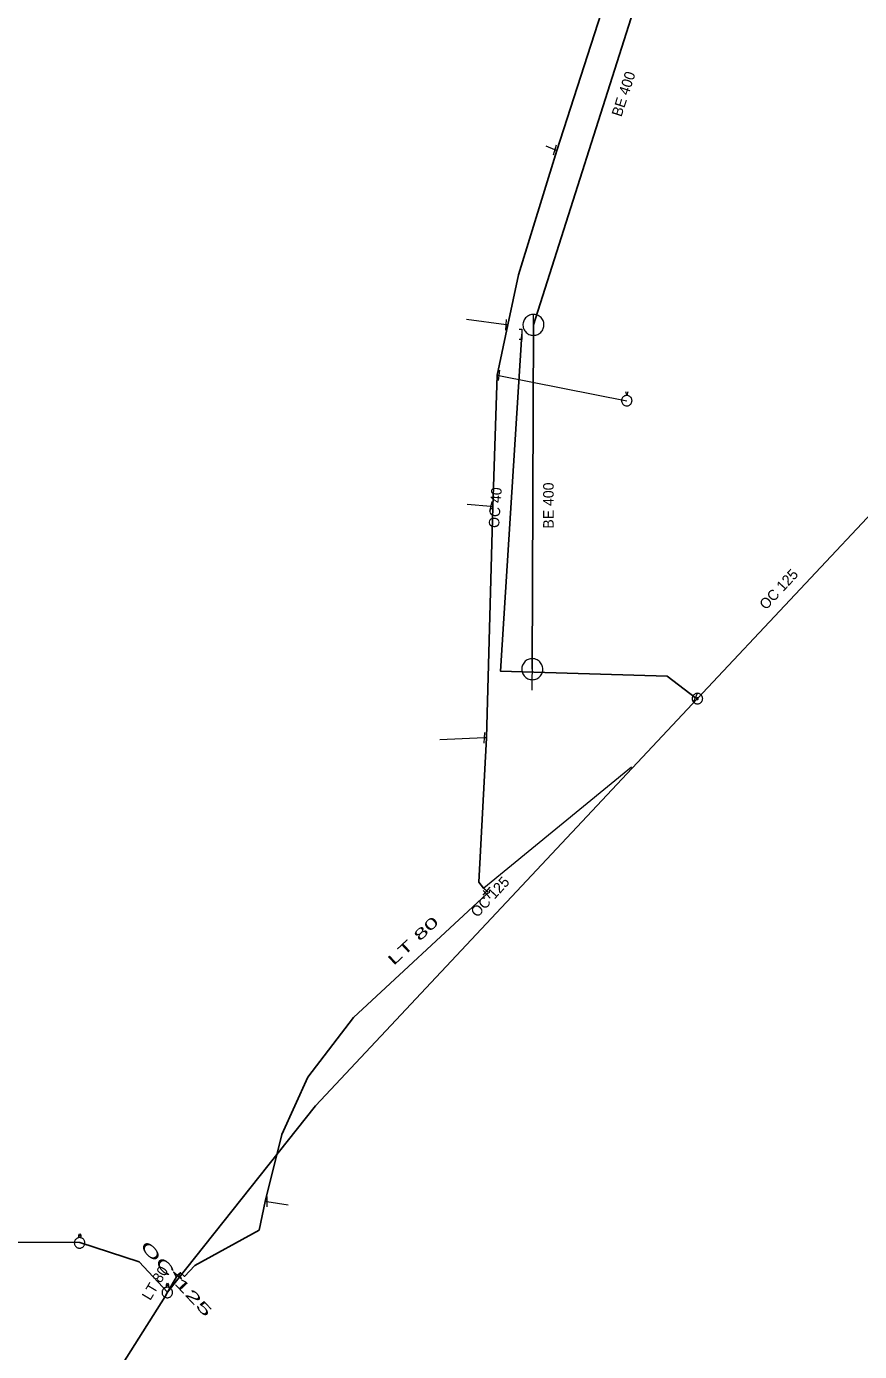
# Model space of a CAD drawing. Extents: x -659250 to -657316, y -997555 to -993684.
# Drawn here: x -658626.7 to -658547.5, y -994219.6 to -994093.6 of the extents above; entities that cross this region are included whole.
import ezdxf

# ---------------------------------------------------------------- set-up
doc = ezdxf.new("R2010")
doc.units = 0
doc.header["$LTSCALE"] = 0.4
doc.layers.add('1', color=7, linetype='Continuous')
for name, color, linetype, lineweight in [('13', 7, 'Continuous', 13), ('14', 7, 'Continuous', 25), ('17', 7, 'Continuous', 25), ('22', 7, 'Continuous', 13), ('23', 7, 'Continuous', 13), ('34', 7, 'Continuous', 13), ('47', 7, 'Continuous', 13)]:
    doc.layers.add(name, color=color, linetype=linetype, lineweight=lineweight)

msp = doc.modelspace()

# ---------------------------------------------------------------- linework, layer by layer
at = {"layer": '13'}
for p, q in [((-658576.454, -994105.35), (-658577.289, -994105.02)), ((-658581.1, -994121.989), (-658584.87, -994121.489)), ((-658581.8, -994126.809), (-658569.629, -994129.21)), ((-658582.539, -994139.27), (-658584.809, -994139.07)), ((-658583.155, -994161.27), (-658587.39, -994161.449)), ((-658583.218, -994175.535), (-658569.18, -994164.039)), ((-658603.864, -994205.37), (-658601.82, -994205.69))]:
    msp.add_line(p, q, dxfattribs=at)
at = {"layer": '14'}
for p, q in [((-658578.5, -994122), (-658563.75, -994075.64)), ((-658578.609, -994154.739), (-658578.5, -994122))]:
    msp.add_line(p, q, dxfattribs=at)
at = {"layer": '14', "lineweight": 13}
for p, q in [((-658576.27, -994105.41), (-658576.454, -994105.35)), ((-658580.94, -994122), (-658581.1, -994121.989)), ((-658581.96, -994126.789), (-658581.8, -994126.809)), ((-658582.379, -994139.309), (-658582.539, -994139.27)), ((-658562.909, -994157.543), (-658563.101, -994157.453)), ((-658582.98, -994161.28), (-658583.155, -994161.27)), ((-658583.26, -994175.57), (-658583.218, -994175.535)), ((-658604.01, -994205.37), (-658603.864, -994205.37))]:
    msp.add_line(p, q, dxfattribs=at)
msp.add_lwpolyline([(-658582.954, -994176.149), (-658582.77, -994175.98), (-658582.945, -994175.84)], dxfattribs=at)
at = {"layer": '17'}
for p, q in [((-658644.456, -994209.127), (-658621.638, -994209.272)), ((-658612.35, -994212.379), (-658613.3, -994213.989))]:
    msp.add_line(p, q, dxfattribs=at)
for points in [[(-658582.945, -994175.84), (-658583.26, -994175.57), (-658583.69, -994175), (-658582.98, -994161.28), (-658582.379, -994139.309), (-658581.96, -994126.789), (-658580.94, -994122), (-658579.92, -994117.25), (-658576.27, -994105.41), (-658571.09, -994089.289), (-658567.85, -994078.489), (-658564.5, -994070.01), (-658561.53, -994061.879), (-658555.69, -994047.969), (-658551.19, -994035.149), (-658548.489, -994027.129), (-658547.875, -994024.539)], [(-658563.101, -994157.453), (-658565.794, -994155.41), (-658581.649, -994154.919), (-658579.62, -994122.895)], [(-658533.629, -994132.381), (-658544.322, -994137.752), (-658562.909, -994157.543)], [(-658613.3, -994213.989), (-658599.228, -994196.254), (-658562.909, -994157.543)], [(-658612.35, -994212.379), (-658612.05, -994212.129), (-658611.69, -994212.48), (-658610.699, -994211.449), (-658604.579, -994208.079), (-658604.01, -994205.37), (-658602.44, -994198.98), (-658599.949, -994193.55), (-658595.629, -994187.85), (-658582.954, -994176.149)], [(-658621.638, -994209.272), (-658615.99, -994211.098), (-658613.3, -994213.989)], [(-658613.3, -994213.989), (-658613.524, -994214.403), (-658623.307, -994229.89), (-658624.14, -994257.537), (-658615.692, -994317.956), (-658606.899, -994352.517), (-658587.086, -994395.585), (-658588.159, -994408.494), (-658589.278, -994412.67), (-658589.404, -994413.139), (-658612.337, -994451.366), (-658612.825, -994451.789), (-658615.8, -994453.061)]]:
    msp.add_lwpolyline(points, dxfattribs=at)
at = {"layer": '22'}
for p, q in [((-658578.5, -994124), (-658578.499, -994121)), ((-658578.609, -994156.739), (-658578.608, -994153.739))]:
    msp.add_line(p, q, dxfattribs=at)
for points in [[(-658577.5, -994122), (-658577.505, -994121.891), (-658577.523, -994121.783), (-658577.553, -994121.677), (-658577.593, -994121.576), (-658577.645, -994121.479), (-658577.707, -994121.389), (-658577.779, -994121.306), (-658577.859, -994121.232), (-658577.947, -994121.166), (-658578.041, -994121.111), (-658578.141, -994121.066), (-658578.246, -994121.033), (-658578.353, -994121.011), (-658578.462, -994121.001), (-658578.572, -994121.003), (-658578.68, -994121.017), (-658578.787, -994121.042), (-658578.89, -994121.079), (-658578.988, -994121.128), (-658579.08, -994121.186), (-658579.166, -994121.255), (-658579.243, -994121.332), (-658579.312, -994121.418), (-658579.371, -994121.51), (-658579.419, -994121.608), (-658579.456, -994121.711), (-658579.482, -994121.818), (-658579.496, -994121.926), (-658579.499, -994122.036), (-658579.489, -994122.145), (-658579.468, -994122.252), (-658579.434, -994122.356), (-658579.39, -994122.456), (-658579.335, -994122.551), (-658579.269, -994122.639), (-658579.195, -994122.719), (-658579.112, -994122.791), (-658579.022, -994122.853), (-658578.926, -994122.905), (-658578.824, -994122.946), (-658578.719, -994122.976), (-658578.611, -994122.994), (-658578.501, -994123), (-658578.392, -994122.994), (-658578.284, -994122.976), (-658578.179, -994122.947), (-658578.077, -994122.906), (-658577.98, -994122.854), (-658577.89, -994122.792), (-658577.807, -994122.721), (-658577.732, -994122.641), (-658577.667, -994122.553), (-658577.611, -994122.459), (-658577.567, -994122.359), (-658577.533, -994122.255), (-658577.511, -994122.147), (-658577.501, -994122.038)], [(-658577.609, -994154.739), (-658577.614, -994154.63), (-658577.632, -994154.522), (-658577.662, -994154.416), (-658577.702, -994154.315), (-658577.754, -994154.218), (-658577.816, -994154.128), (-658577.888, -994154.045), (-658577.968, -994153.971), (-658578.056, -994153.905), (-658578.15, -994153.85), (-658578.25, -994153.805), (-658578.355, -994153.772), (-658578.462, -994153.75), (-658578.571, -994153.74), (-658578.681, -994153.742), (-658578.789, -994153.756), (-658578.896, -994153.781), (-658578.999, -994153.818), (-658579.097, -994153.867), (-658579.189, -994153.925), (-658579.275, -994153.994), (-658579.352, -994154.071), (-658579.421, -994154.157), (-658579.48, -994154.249), (-658579.528, -994154.347), (-658579.565, -994154.45), (-658579.591, -994154.557), (-658579.605, -994154.665), (-658579.608, -994154.775), (-658579.598, -994154.884), (-658579.577, -994154.991), (-658579.543, -994155.095), (-658579.499, -994155.195), (-658579.444, -994155.29), (-658579.378, -994155.378), (-658579.304, -994155.458), (-658579.221, -994155.53), (-658579.131, -994155.592), (-658579.035, -994155.644), (-658578.933, -994155.685), (-658578.828, -994155.715), (-658578.72, -994155.733), (-658578.61, -994155.739), (-658578.501, -994155.733), (-658578.393, -994155.715), (-658578.288, -994155.686), (-658578.186, -994155.645), (-658578.089, -994155.593), (-658577.999, -994155.531), (-658577.916, -994155.46), (-658577.841, -994155.38), (-658577.776, -994155.292), (-658577.72, -994155.198), (-658577.676, -994155.098), (-658577.642, -994154.994), (-658577.62, -994154.886), (-658577.61, -994154.777)]]:
    msp.add_lwpolyline(points, close=True, dxfattribs=at)
at = {"layer": '23'}
for p, q in [((-658621.551, -994208.624), (-658621.747, -994208.624)), ((-658613.213, -994213.341), (-658613.409, -994213.341))]:
    msp.add_line(p, q, dxfattribs=at)
msp.add_lwpolyline([(-658569.13, -994129.21), (-658569.136, -994129.133), (-658569.154, -994129.058), (-658569.183, -994128.986), (-658569.223, -994128.92), (-658569.273, -994128.861), (-658569.331, -994128.81), (-658569.396, -994128.769), (-658569.467, -994128.739), (-658569.542, -994128.72), (-658569.619, -994128.712), (-658569.696, -994128.717), (-658569.772, -994128.733), (-658569.844, -994128.761), (-658569.91, -994128.8), (-658569.97, -994128.849), (-658570.022, -994128.906), (-658570.065, -994128.971), (-658570.096, -994129.041), (-658570.117, -994129.115), (-658570.126, -994129.192), (-658570.123, -994129.269), (-658570.108, -994129.345), (-658570.081, -994129.418), (-658570.044, -994129.485), (-658569.996, -994129.546), (-658569.94, -994129.599), (-658569.876, -994129.642), (-658569.806, -994129.675), (-658569.732, -994129.697), (-658569.656, -994129.707), (-658569.578, -994129.705), (-658569.502, -994129.691), (-658569.429, -994129.666), (-658569.361, -994129.63), (-658569.3, -994129.583), (-658569.246, -994129.528), (-658569.201, -994129.465), (-658569.167, -994129.396), (-658569.144, -994129.322), (-658569.132, -994129.246)], close=True, dxfattribs=at)
for points in [[(-658569.521, -994128.362), (-658569.624, -994128.673), (-658569.727, -994128.362)], [(-658621.161, -994209.289), (-658621.163, -994209.236), (-658621.172, -994209.184), (-658621.187, -994209.135), (-658621.206, -994209.086), (-658621.23, -994209.04), (-658621.26, -994208.996), (-658621.293, -994208.956), (-658621.33, -994208.92), (-658621.371, -994208.887), (-658621.415, -994208.859), (-658621.462, -994208.835), (-658621.512, -994208.817), (-658621.562, -994208.804), (-658621.613, -994208.797), (-658621.665, -994208.794), (-658621.719, -994208.798), (-658621.769, -994208.806), (-658621.821, -994208.821), (-658621.868, -994208.839), (-658621.915, -994208.863), (-658621.959, -994208.894), (-658621.999, -994208.927), (-658622.036, -994208.965), (-658622.069, -994209.005), (-658622.096, -994209.049), (-658622.119, -994209.097), (-658622.137, -994209.145), (-658622.15, -994209.196), (-658622.157, -994209.248), (-658622.161, -994209.3), (-658622.158, -994209.352), (-658622.149, -994209.404), (-658622.135, -994209.455), (-658622.116, -994209.503), (-658622.091, -994209.548), (-658622.062, -994209.592), (-658622.029, -994209.633), (-658621.991, -994209.67), (-658621.95, -994209.702)], [(-658621.821, -994208.821), (-658621.868, -994208.839), (-658621.915, -994208.863), (-658621.959, -994208.894), (-658621.999, -994208.927), (-658622.036, -994208.965), (-658622.069, -994209.005), (-658622.096, -994209.049), (-658622.119, -994209.097), (-658622.137, -994209.145), (-658622.15, -994209.196), (-658622.157, -994209.248), (-658622.161, -994209.3), (-658622.158, -994209.352), (-658622.149, -994209.404), (-658622.135, -994209.455), (-658622.116, -994209.503), (-658622.091, -994209.548), (-658622.062, -994209.592), (-658622.029, -994209.633), (-658621.991, -994209.67), (-658621.95, -994209.702), (-658621.907, -994209.73), (-658621.859, -994209.753), (-658621.811, -994209.772), (-658621.759, -994209.784), (-658621.708, -994209.791), (-658621.656, -994209.794), (-658621.604, -994209.79), (-658621.552, -994209.782), (-658621.501, -994209.768), (-658621.453, -994209.748), (-658621.406, -994209.724), (-658621.363, -994209.696), (-658621.323, -994209.661), (-658621.286, -994209.625), (-658621.254, -994209.584), (-658621.225, -994209.539), (-658621.202, -994209.492), (-658621.184, -994209.443)], [(-658621.95, -994209.702), (-658621.907, -994209.73), (-658621.859, -994209.753), (-658621.811, -994209.772), (-658621.759, -994209.784), (-658621.708, -994209.791), (-658621.656, -994209.794), (-658621.604, -994209.79), (-658621.552, -994209.782), (-658621.501, -994209.768), (-658621.453, -994209.748), (-658621.406, -994209.724), (-658621.363, -994209.696), (-658621.323, -994209.661), (-658621.286, -994209.625), (-658621.254, -994209.584), (-658621.225, -994209.539), (-658621.202, -994209.492), (-658621.184, -994209.443), (-658621.172, -994209.392), (-658621.164, -994209.341), (-658621.161, -994209.289), (-658621.163, -994209.236), (-658621.172, -994209.184), (-658621.187, -994209.135), (-658621.206, -994209.086), (-658621.23, -994209.04), (-658621.26, -994208.996), (-658621.293, -994208.956), (-658621.33, -994208.92), (-658621.371, -994208.887), (-658621.415, -994208.859), (-658621.462, -994208.835), (-658621.512, -994208.817), (-658621.562, -994208.804), (-658621.613, -994208.797), (-658621.665, -994208.794), (-658621.719, -994208.798), (-658621.769, -994208.806), (-658621.821, -994208.821)], [(-658621.747, -994208.721), (-658621.747, -994208.572), (-658621.648, -994208.421), (-658621.551, -994208.572), (-658621.551, -994208.721)], [(-658621.184, -994209.443), (-658621.172, -994209.392), (-658621.164, -994209.341), (-658621.161, -994209.289)], [(-658613.409, -994213.438), (-658613.409, -994213.289), (-658613.31, -994213.138), (-658613.213, -994213.289), (-658613.213, -994213.438)], [(-658612.823, -994214.006), (-658612.825, -994213.953), (-658612.834, -994213.901), (-658612.849, -994213.852), (-658612.868, -994213.803), (-658612.892, -994213.757), (-658612.922, -994213.713), (-658612.955, -994213.673), (-658612.992, -994213.637), (-658613.033, -994213.604), (-658613.077, -994213.576), (-658613.124, -994213.552), (-658613.174, -994213.534), (-658613.224, -994213.521), (-658613.275, -994213.514), (-658613.327, -994213.511), (-658613.381, -994213.515), (-658613.431, -994213.523), (-658613.483, -994213.538), (-658613.53, -994213.556), (-658613.577, -994213.58), (-658613.621, -994213.611), (-658613.661, -994213.644), (-658613.698, -994213.682), (-658613.731, -994213.722), (-658613.758, -994213.766), (-658613.781, -994213.814), (-658613.799, -994213.862), (-658613.812, -994213.913), (-658613.819, -994213.965), (-658613.823, -994214.017), (-658613.82, -994214.069), (-658613.811, -994214.121), (-658613.797, -994214.172), (-658613.778, -994214.22), (-658613.753, -994214.265), (-658613.724, -994214.309), (-658613.691, -994214.35), (-658613.653, -994214.387), (-658613.612, -994214.419)], [(-658613.483, -994213.538), (-658613.53, -994213.556), (-658613.577, -994213.58), (-658613.621, -994213.611), (-658613.661, -994213.644), (-658613.698, -994213.682), (-658613.731, -994213.722), (-658613.758, -994213.766), (-658613.781, -994213.814), (-658613.799, -994213.862), (-658613.812, -994213.913), (-658613.819, -994213.965), (-658613.823, -994214.017), (-658613.82, -994214.069), (-658613.811, -994214.121), (-658613.797, -994214.172), (-658613.778, -994214.22), (-658613.753, -994214.265), (-658613.724, -994214.309), (-658613.691, -994214.35), (-658613.653, -994214.387), (-658613.612, -994214.419), (-658613.569, -994214.447), (-658613.521, -994214.47), (-658613.473, -994214.489), (-658613.421, -994214.501), (-658613.37, -994214.508), (-658613.318, -994214.511), (-658613.266, -994214.507), (-658613.214, -994214.499), (-658613.163, -994214.485), (-658613.115, -994214.465), (-658613.068, -994214.441), (-658613.025, -994214.413), (-658612.985, -994214.378), (-658612.948, -994214.342), (-658612.916, -994214.301), (-658612.887, -994214.256), (-658612.864, -994214.209), (-658612.846, -994214.16)], [(-658613.612, -994214.419), (-658613.569, -994214.447), (-658613.521, -994214.47), (-658613.473, -994214.489), (-658613.421, -994214.501), (-658613.37, -994214.508), (-658613.318, -994214.511), (-658613.266, -994214.507), (-658613.214, -994214.499), (-658613.163, -994214.485), (-658613.115, -994214.465), (-658613.068, -994214.441), (-658613.025, -994214.413), (-658612.985, -994214.378), (-658612.948, -994214.342), (-658612.916, -994214.301), (-658612.887, -994214.256), (-658612.864, -994214.209), (-658612.846, -994214.16), (-658612.834, -994214.109), (-658612.826, -994214.058), (-658612.823, -994214.006), (-658612.825, -994213.953), (-658612.834, -994213.901), (-658612.849, -994213.852), (-658612.868, -994213.803), (-658612.892, -994213.757), (-658612.922, -994213.713), (-658612.955, -994213.673), (-658612.992, -994213.637), (-658613.033, -994213.604), (-658613.077, -994213.576), (-658613.124, -994213.552), (-658613.174, -994213.534), (-658613.224, -994213.521), (-658613.275, -994213.514), (-658613.327, -994213.511), (-658613.381, -994213.515), (-658613.431, -994213.523), (-658613.483, -994213.538)], [(-658612.846, -994214.16), (-658612.834, -994214.109), (-658612.826, -994214.058), (-658612.823, -994214.006)]]:
    msp.add_lwpolyline(points, dxfattribs=at)
at = {"layer": '34'}
for p, q in [((-658576.607, -994105.825), (-658576.299, -994104.874)), ((-658581.13, -994122.488), (-658581.068, -994121.49)), ((-658581.738, -994126.312), (-658581.862, -994127.305)), ((-658582.659, -994139.755), (-658582.417, -994138.785)), ((-658562.892, -994156.998), (-658563.31, -994157.906)), ((-658583.183, -994161.769), (-658583.125, -994160.77)), ((-658583.559, -994175.169), (-658582.877, -994175.901)), ((-658583.27, -994176.219), (-658582.619, -994175.46)), ((-658583.292, -994175.781), (-658582.616, -994176.517)), ((-658603.864, -994204.87), (-658603.864, -994205.87))]:
    msp.add_line(p, q, dxfattribs=at)
at = {"layer": '47'}
msp.add_line((-658612.745, -994212.057), (-658612.504, -994212.507), dxfattribs=at)
for points in [[(-658579.872, -994122.399), (-658579.62, -994122.399), (-658579.62, -994123.391), (-658579.872, -994123.391)], [(-658612.745, -994212.057), (-658611.954, -994212.7), (-658612.195, -994212.25)]]:
    msp.add_lwpolyline(points, dxfattribs=at)
for points in [[(-658562.409, -994157.543), (-658562.412, -994157.49), (-658562.42, -994157.438), (-658562.434, -994157.389), (-658562.451, -994157.34), (-658562.476, -994157.293), (-658562.505, -994157.249), (-658562.538, -994157.208), (-658562.575, -994157.171), (-658562.615, -994157.139), (-658562.659, -994157.11), (-658562.706, -994157.085), (-658562.755, -994157.068), (-658562.804, -994157.054), (-658562.857, -994157.046), (-658562.909, -994157.043), (-658562.961, -994157.046), (-658563.013, -994157.054), (-658563.064, -994157.068), (-658563.112, -994157.085), (-658563.159, -994157.11), (-658563.203, -994157.139), (-658563.244, -994157.171), (-658563.281, -994157.208), (-658563.314, -994157.249), (-658563.342, -994157.293), (-658563.366, -994157.34), (-658563.385, -994157.389), (-658563.397, -994157.438), (-658563.406, -994157.49), (-658563.409, -994157.543), (-658563.406, -994157.595), (-658563.397, -994157.647), (-658563.385, -994157.698), (-658563.366, -994157.745), (-658563.342, -994157.793), (-658563.314, -994157.837), (-658563.281, -994157.877), (-658563.244, -994157.914), (-658563.203, -994157.948), (-658563.159, -994157.975), (-658563.112, -994158), (-658563.064, -994158.019), (-658563.013, -994158.031), (-658562.961, -994158.039), (-658562.909, -994158.043), (-658562.857, -994158.039), (-658562.804, -994158.031), (-658562.755, -994158.019), (-658562.706, -994158), (-658562.659, -994157.975), (-658562.615, -994157.948), (-658562.575, -994157.914), (-658562.538, -994157.877), (-658562.505, -994157.837), (-658562.476, -994157.793), (-658562.451, -994157.745), (-658562.434, -994157.698), (-658562.42, -994157.647), (-658562.412, -994157.595)], [(-658562.826, -994157.543), (-658562.826, -994157.534), (-658562.829, -994157.526), (-658562.831, -994157.517), (-658562.834, -994157.509), (-658562.838, -994157.502), (-658562.843, -994157.495), (-658562.848, -994157.487), (-658562.853, -994157.482), (-658562.861, -994157.477), (-658562.868, -994157.472), (-658562.875, -994157.468), (-658562.884, -994157.465), (-658562.892, -994157.463), (-658562.9, -994157.46), (-658562.909, -994157.46), (-658562.918, -994157.46), (-658562.926, -994157.463), (-658562.934, -994157.465), (-658562.942, -994157.468), (-658562.95, -994157.472), (-658562.956, -994157.477), (-658562.964, -994157.482), (-658562.97, -994157.487), (-658562.976, -994157.495), (-658562.98, -994157.502), (-658562.983, -994157.509), (-658562.987, -994157.517), (-658562.989, -994157.526), (-658562.991, -994157.534), (-658562.991, -994157.543), (-658562.991, -994157.551), (-658562.989, -994157.559), (-658562.987, -994157.568), (-658562.983, -994157.576), (-658562.98, -994157.583), (-658562.976, -994157.59), (-658562.97, -994157.598), (-658562.964, -994157.603), (-658562.956, -994157.61), (-658562.95, -994157.614), (-658562.942, -994157.617), (-658562.934, -994157.62), (-658562.926, -994157.622), (-658562.918, -994157.625), (-658562.909, -994157.625), (-658562.9, -994157.625), (-658562.892, -994157.622), (-658562.884, -994157.62), (-658562.875, -994157.617), (-658562.868, -994157.614), (-658562.861, -994157.61), (-658562.853, -994157.603), (-658562.848, -994157.598), (-658562.843, -994157.59), (-658562.838, -994157.583), (-658562.834, -994157.576), (-658562.831, -994157.568), (-658562.829, -994157.559), (-658562.826, -994157.551)]]:
    msp.add_lwpolyline(points, close=True, dxfattribs=at)

# ---------------------------------------------------------------- texts
at = {"layer": '1'}
for s, rotation, p in [('BE 400', 72, (-658570.142, -994102.28)), ('OC 40 ', 86, (-658581.776, -994141.338)), ('BE 400', 90, (-658576.579, -994141.376)), ('OC 125', 47, (-658556.387, -994149.159)), ('OC 125', 47, (-658583.839, -994178.411)), ('LT 80 ', 59, (-658614.943, -994214.837))]:
    msp.add_text(s, height=1, rotation=rotation, dxfattribs=at).set_placement(p)
for s, rotation, width, p in [('LT 80 ', 43, 1.75, (-658591.796, -994182.971)), ('OC 125', 313, 2, (-658615.966, -994209.675))]:
    msp.add_text(s, height=1, rotation=rotation, dxfattribs=dict(at, width=width)).set_placement(p)

doc.saveas('drawing.dxf')
